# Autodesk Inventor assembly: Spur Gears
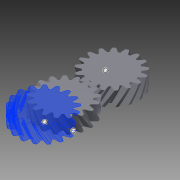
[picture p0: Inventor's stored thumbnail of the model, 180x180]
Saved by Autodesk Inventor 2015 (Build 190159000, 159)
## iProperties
Created: 2014-06
Part Number: Spur Gears
Document SubType Name: Assembly
Designer: User
Categories: <?xml version="1.0" encoding="UTF-16"?> <MemberInstance><Categories><FamilyTemplate/><ParamToTemplateMap><ParamToTemplate><ParamToTemplate CategoryParameter="//
ClientObjectVersion: 1
Author: User
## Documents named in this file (3)
- Z:\CAD Files\Misc\Helical_Gear_Assembly\Design Accelerator\Spur Gears1.iam
- Z:\CAD Files\Misc\Helical_Gear_Assembly\Design Accelerator\Spur Gear11.ipt
- Z:\CAD Files\Misc\Helical_Gear_Assembly\Design Accelerator\Spur Gear21.ipt
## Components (2 placed, 2 different names)
1. Spur Gear1:1 — Rotation:1
2. Spur Gear2:1 — Rotation:1
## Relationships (1: RelateRotation 1)
- Rotation:1 [RelateRotation]: Spur Gear1:1 ↔ Spur Gear2:1
